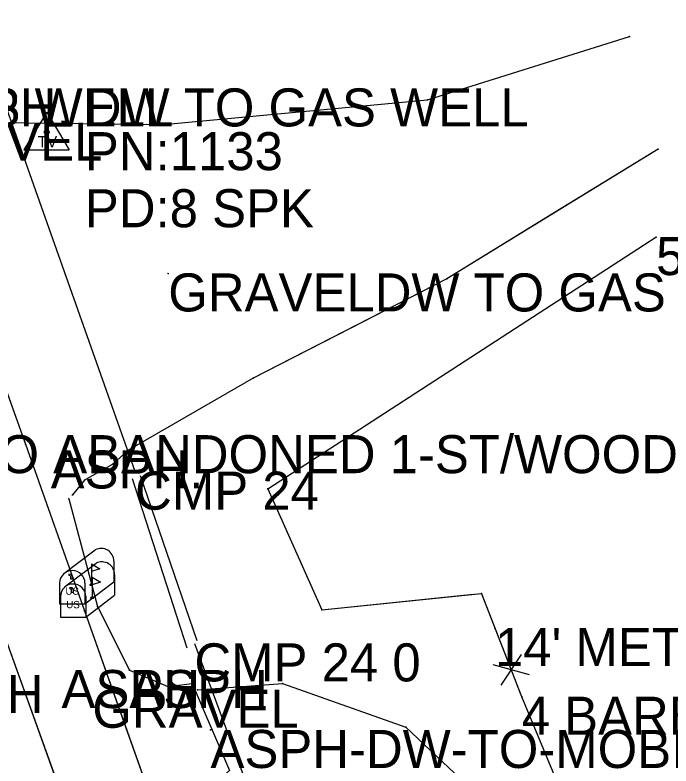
# Model space of a CAD drawing. Extents: x 1050807 to 1053552, y 395828 to 398415.
# Drawn here: x 1052635.6 to 1052721.8, y 396242.6 to 396341.3 of the extents above; entities that cross this region are included whole.
import ezdxf

# ---------------------------------------------------------------- set-up
doc = ezdxf.new("R2010")
doc.units = 0
for name, color, linetype in [('S_BREAKLINE_ANNOT', 7, 'Continuous'), ('S_DITCHLINE', 7, 'Continuous'), ('S_DRIVEWAY', 7, 'Continuous'), ('S_DRIVEWAY_ANNOT', 7, 'Continuous'), ('S_EDGE_PAVEMENT', 7, 'Continuous'), ('S_FENCE', 7, 'Continuous'), ('S_FENCE_ANNOT', 7, 'Continuous'), ('S_GATE_ANNOT', 7, 'Continuous'), ('S_MAILBOX', 7, 'Continuous'), ('S_MSC_PT_SYM', 7, 'Continuous'), ('S_PAVEMENT_CROWN', 7, 'Continuous'), ('S_RDW_PT_SYM', 7, 'Continuous'), ('S_SECONDARY_CTL', 7, 'Continuous'), ('S_SECONDARY_CTL_ANNOT', 7, 'Continuous'), ('S_SHOULDER', 7, 'Continuous'), ('S_SHOULDER_ANNOT', 7, 'Continuous'), ('S_SIDE_DRAIN', 7, 'Continuous'), ('S_SIDE_DRAIN_ANNOT', 7, 'Continuous'), ('S_SURVEY_TEXT_ANNOT', 7, 'Continuous')]:
    doc.layers.add(name, color=color, linetype=linetype)

msp = doc.modelspace()

# ---------------------------------------------------------------- linework, layer by layer
at = {"layer": 'S_DITCHLINE'}
for p, q in [((1052659.554, 396259.093), (1052652.113, 396280.771)), ((1052650.985, 396280.428), (1052658.169, 396258.14))]:
    msp.add_line(p, q, dxfattribs=at)
for points in [[(1052659.554, 396259.093), (1052652.113, 396280.771)], [(1052650.985, 396280.428), (1052658.169, 396258.14)]]:
    msp.add_lwpolyline(points, dxfattribs=at)
at = {"layer": 'S_DRIVEWAY'}
for p, q in [((1052689.815, 396330.179), (1052716.376, 396338.498)), ((1052655.11, 396326.952), (1052689.815, 396330.179)), ((1052633.806, 396327.202), (1052655.11, 396326.952)), ((1052720.133, 396323.689), (1052692.367, 396306.673)), ((1052692.367, 396306.673), (1052666.897, 396293.612)), ((1052666.897, 396293.612), (1052650.436, 396284.075)), ((1052650.432, 396284.099), (1052648.475, 396282.317)), ((1052648.475, 396282.317), (1052644.746, 396280.181)), ((1052644.746, 396280.181), (1052643.153, 396278.243)), ((1052650.633, 396255.24), (1052655.682, 396253.093)), ((1052655.682, 396253.093), (1052658.899, 396253.455)), ((1052658.899, 396253.455), (1052663.794, 396242.041)), ((1052659.599, 396252.648), (1052670.746, 396253.477)), ((1052670.746, 396253.477), (1052686.966, 396247.747)), ((1052686.966, 396247.747), (1052693.355, 396241.694))]:
    msp.add_line(p, q, dxfattribs=at)
for points in [[(1052633.806, 396327.202), (1052655.11, 396326.952), (1052672.463, 396328.566), (1052689.815, 396330.179), (1052703.095, 396334.339), (1052716.376, 396338.498)], [(1052720.133, 396323.689), (1052706.25, 396315.181), (1052692.367, 396306.673), (1052679.632, 396300.142), (1052666.897, 396293.612), (1052650.436, 396284.075)], [(1052650.432, 396284.099), (1052648.475, 396282.317), (1052644.746, 396280.181), (1052643.153, 396278.243)], [(1052650.633, 396255.24), (1052655.682, 396253.093), (1052658.899, 396253.455), (1052663.794, 396242.041), (1052658.163, 396237.039), (1052657.671, 396236.529)], [(1052659.599, 396252.648), (1052670.746, 396253.477), (1052686.966, 396247.747), (1052693.355, 396241.694), (1052703.814, 396231.564), (1052710.608, 396211.533), (1052717.403, 396191.501), (1052724.49, 396172.289), (1052731.576, 396153.078), (1052738.663, 396133.866), (1052745.75, 396114.654), (1052754.61, 396095.247), (1052763.47, 396075.839), (1052772.33, 396056.432), (1052781.19, 396037.024), (1052788.618, 396024.663), (1052796.046, 396012.301), (1052803.473, 395999.94), (1052810.901, 395987.578), (1052815.523, 395970.218), (1052820.461, 395954.627), (1052808.405, 395951.524)]]:
    msp.add_lwpolyline(points, dxfattribs=at)
at = {"layer": 'S_EDGE_PAVEMENT'}
for p, q in [((1052620.452, 396330.901), (1052636.983, 396284.917)), ((1052636.983, 396284.917), (1052644.723, 396263.019)), ((1052644.723, 396263.019), (1052655.116, 396233.764))]:
    msp.add_line(p, q, dxfattribs=at)
msp.add_lwpolyline([(1052574.206, 396459.412), (1052580.36, 396442.372), (1052586.514, 396425.332), (1052593.054, 396407.062), (1052599.594, 396388.791), (1052606.141, 396370.632), (1052612.688, 396352.473), (1052620.452, 396330.901), (1052628.718, 396307.909), (1052636.983, 396284.917), (1052644.723, 396263.019), (1052649.92, 396248.391), (1052655.116, 396233.764)], dxfattribs=at)
at = {"layer": 'S_FENCE'}
for p, q in [((1052668.814, 396279.063), (1052719.801, 396312.149)), ((1052668.814, 396279.038), (1052675.933, 396263.161)), ((1052675.933, 396263.161), (1052696.925, 396265.307)), ((1052699.491, 396253.229), (1052702.163, 396257.286)), ((1052703.198, 396254.615), (1052698.456, 396255.901))]:
    msp.add_line(p, q, dxfattribs=at)
for points in [[(1052668.814, 396279.038), (1052675.933, 396263.161)], [(1052675.933, 396263.161), (1052695.829, 396265.195)], [(1052721.509, 396192.743), (1052710.07, 396232.831), (1052702.193, 396251.73), (1052696.925, 396265.332)], [(1052700.309, 396256.594), (1052696.925, 396265.332)], [(1052714.931, 396215.794), (1052710.07, 396232.831), (1052702.193, 396251.73), (1052701.549, 396253.395)]]:
    msp.add_lwpolyline(points, dxfattribs=at)
at = {"layer": 'S_MAILBOX'}
for p, q in [((1052642.028, 396267.927), (1052646.162, 396271.035)), ((1052642.13, 396266.156), (1052646.265, 396269.264)), ((1052645.643, 396269.215), (1052645.643, 396266.5)), ((1052648.594, 396269.561), (1052648.594, 396266.846)), ((1052645.746, 396267.445), (1052645.746, 396264.73)), ((1052648.696, 396267.791), (1052648.696, 396265.076)), ((1052641.474, 396266.652), (1052641.474, 396263.937)), ((1052644.798, 396263.937), (1052648.594, 396266.846)), ((1052644.798, 396266.652), (1052644.798, 396263.937)), ((1052644.901, 396262.167), (1052648.696, 396265.076)), ((1052641.474, 396263.937), (1052644.798, 396263.937)), ((1052641.576, 396264.882), (1052641.576, 396262.167)), ((1052644.901, 396264.882), (1052644.901, 396262.167)), ((1052641.576, 396262.167), (1052644.901, 396262.167))]:
    msp.add_line(p, q, dxfattribs=at)
for points in [[(1052645.643, 396269.215), (1052646.751, 396268.55), (1052645.643, 396268.204)], [(1052642.658, 396267.768), (1052642.88, 396267.629), (1052642.88, 396267.241), (1052643.184, 396267.241), (1052643.184, 396267.601), (1052642.99, 396267.851), (1052642.658, 396267.795)], [(1052645.746, 396267.445), (1052646.854, 396266.78), (1052645.746, 396266.433)], [(1052642.761, 396265.997), (1052642.982, 396265.858), (1052642.982, 396265.471), (1052643.287, 396265.471), (1052643.287, 396265.831), (1052643.093, 396266.08), (1052642.761, 396266.025)]]:
    msp.add_lwpolyline(points, dxfattribs=at)
for centre, end in [((1052646.931, 396269.561), 117.57184), ((1052647.034, 396267.791), 117.57184), ((1052643.136, 396266.652), 180), ((1052643.238, 396264.882), 180)]:
    msp.add_arc(centre, 1.662, 0, end, dxfattribs=at)
for centre in [(1052645.643, 396266.5), (1052645.746, 396264.73)]:
    msp.add_ellipse(centre, major_axis=(0.145, 0.132), ratio=0.564646, dxfattribs=at)
at = {"layer": 'S_MSC_PT_SYM'}
for points in [[(1052719.851, 396312.149), (1052719.851, 396312.199), (1052719.851, 396312.149), (1052719.801, 396312.149), (1052719.851, 396312.149), (1052719.851, 396312.099), (1052719.851, 396312.149), (1052719.901, 396312.149)], [(1052655.747, 396307.37), (1052655.747, 396307.42), (1052655.747, 396307.37), (1052655.697, 396307.37), (1052655.747, 396307.37), (1052655.747, 396307.32), (1052655.747, 396307.37), (1052655.797, 396307.37)], [(1052668.814, 396279.038), (1052668.814, 396279.088), (1052668.814, 396279.038), (1052668.764, 396279.038), (1052668.814, 396279.038), (1052668.814, 396278.988), (1052668.814, 396279.038), (1052668.864, 396279.038)], [(1052696.925, 396265.307), (1052696.925, 396265.357), (1052696.925, 396265.307), (1052696.875, 396265.307), (1052696.925, 396265.307), (1052696.925, 396265.257), (1052696.925, 396265.307), (1052696.975, 396265.307)], [(1052675.933, 396263.161), (1052675.933, 396263.211), (1052675.933, 396263.161), (1052675.883, 396263.161), (1052675.933, 396263.161), (1052675.933, 396263.111), (1052675.933, 396263.161), (1052675.983, 396263.161)], [(1052698.682, 396260.752), (1052698.682, 396260.802), (1052698.682, 396260.752), (1052698.632, 396260.752), (1052698.682, 396260.752), (1052698.682, 396260.702), (1052698.682, 396260.752), (1052698.732, 396260.752)], [(1052702.193, 396251.73), (1052702.193, 396251.78), (1052702.193, 396251.73), (1052702.143, 396251.73), (1052702.193, 396251.73), (1052702.193, 396251.68), (1052702.193, 396251.73), (1052702.243, 396251.73)], [(1052661.294, 396247.359), (1052661.294, 396247.409), (1052661.294, 396247.359), (1052661.244, 396247.359), (1052661.294, 396247.359), (1052661.294, 396247.309), (1052661.294, 396247.359), (1052661.344, 396247.359)]]:
    msp.add_lwpolyline(points, dxfattribs=at)
at = {"layer": 'S_PAVEMENT_CROWN'}
msp.add_line((1052634.394, 396259.265), (1052644.906, 396230.007), dxfattribs=at)
msp.add_lwpolyline([(1052563.845, 396455.267), (1052570.025, 396438.384), (1052576.205, 396421.501), (1052582.809, 396403.173), (1052589.412, 396384.846), (1052595.833, 396366.903), (1052602.254, 396348.959), (1052609.906, 396326.87), (1052617.924, 396304.161), (1052625.942, 396281.452), (1052634.394, 396259.265), (1052639.65, 396244.636), (1052644.906, 396230.007)], dxfattribs=at)
at = {"layer": 'S_RDW_PT_SYM'}
for points in [[(1052716.376, 396338.498), (1052716.376, 396338.548), (1052716.376, 396338.498), (1052716.326, 396338.498), (1052716.376, 396338.498), (1052716.376, 396338.448), (1052716.376, 396338.498), (1052716.426, 396338.498)], [(1052689.815, 396330.179), (1052689.815, 396330.229), (1052689.815, 396330.179), (1052689.765, 396330.179), (1052689.815, 396330.179), (1052689.815, 396330.129), (1052689.815, 396330.179), (1052689.865, 396330.179)], [(1052655.11, 396326.952), (1052655.11, 396327.002), (1052655.11, 396326.952), (1052655.06, 396326.952), (1052655.11, 396326.952), (1052655.11, 396326.902), (1052655.11, 396326.952), (1052655.16, 396326.952)], [(1052720.133, 396323.689), (1052720.133, 396323.739), (1052720.133, 396323.689), (1052720.083, 396323.689), (1052720.133, 396323.689), (1052720.133, 396323.639), (1052720.133, 396323.689), (1052720.183, 396323.689)], [(1052692.367, 396306.673), (1052692.367, 396306.723), (1052692.367, 396306.673), (1052692.317, 396306.673), (1052692.367, 396306.673), (1052692.367, 396306.623), (1052692.367, 396306.673), (1052692.417, 396306.673)], [(1052666.897, 396293.612), (1052666.897, 396293.662), (1052666.897, 396293.612), (1052666.847, 396293.612), (1052666.897, 396293.612), (1052666.897, 396293.562), (1052666.897, 396293.612), (1052666.947, 396293.612)], [(1052636.983, 396284.917), (1052636.983, 396284.967), (1052636.983, 396284.917), (1052636.933, 396284.917), (1052636.983, 396284.917), (1052636.983, 396284.867), (1052636.983, 396284.917), (1052637.033, 396284.917)], [(1052650.432, 396284.099), (1052650.432, 396284.149), (1052650.432, 396284.099), (1052650.382, 396284.099), (1052650.432, 396284.099), (1052650.432, 396284.049), (1052650.432, 396284.099), (1052650.482, 396284.099)], [(1052650.436, 396284.075), (1052650.436, 396284.125), (1052650.436, 396284.075), (1052650.386, 396284.075), (1052650.436, 396284.075), (1052650.436, 396284.025), (1052650.436, 396284.075), (1052650.486, 396284.075)], [(1052648.475, 396282.317), (1052648.475, 396282.367), (1052648.475, 396282.317), (1052648.425, 396282.317), (1052648.475, 396282.317), (1052648.475, 396282.267), (1052648.475, 396282.317), (1052648.525, 396282.317)], [(1052644.746, 396280.181), (1052644.746, 396280.231), (1052644.746, 396280.181), (1052644.696, 396280.181), (1052644.746, 396280.181), (1052644.746, 396280.131), (1052644.746, 396280.181), (1052644.796, 396280.181)], [(1052642.667, 396277.739), (1052642.667, 396277.789), (1052642.667, 396277.739), (1052642.617, 396277.739), (1052642.667, 396277.739), (1052642.667, 396277.689), (1052642.667, 396277.739), (1052642.717, 396277.739)], [(1052643.153, 396278.243), (1052643.153, 396278.293), (1052643.153, 396278.243), (1052643.103, 396278.243), (1052643.153, 396278.243), (1052643.153, 396278.193), (1052643.153, 396278.243), (1052643.203, 396278.243)], [(1052644.723, 396263.019), (1052644.723, 396263.069), (1052644.723, 396263.019), (1052644.673, 396263.019), (1052644.723, 396263.019), (1052644.723, 396262.969), (1052644.723, 396263.019), (1052644.773, 396263.019)], [(1052646.452, 396263.595), (1052646.452, 396263.645), (1052646.452, 396263.595), (1052646.402, 396263.595), (1052646.452, 396263.595), (1052646.452, 396263.545), (1052646.452, 396263.595), (1052646.502, 396263.595)], [(1052650.633, 396255.24), (1052650.633, 396255.29), (1052650.633, 396255.24), (1052650.583, 396255.24), (1052650.633, 396255.24), (1052650.633, 396255.19), (1052650.633, 396255.24), (1052650.683, 396255.24)], [(1052650.633, 396255.24), (1052650.633, 396255.29), (1052650.633, 396255.24), (1052650.583, 396255.24), (1052650.633, 396255.24), (1052650.633, 396255.19), (1052650.633, 396255.24), (1052650.683, 396255.24)], [(1052655.682, 396253.093), (1052655.682, 396253.143), (1052655.682, 396253.093), (1052655.632, 396253.093), (1052655.682, 396253.093), (1052655.682, 396253.043), (1052655.682, 396253.093), (1052655.732, 396253.093)], [(1052658.899, 396253.455), (1052658.899, 396253.505), (1052658.899, 396253.455), (1052658.849, 396253.455), (1052658.899, 396253.455), (1052658.899, 396253.405), (1052658.899, 396253.455), (1052658.949, 396253.455)], [(1052670.746, 396253.477), (1052670.746, 396253.527), (1052670.746, 396253.477), (1052670.696, 396253.477), (1052670.746, 396253.477), (1052670.746, 396253.427), (1052670.746, 396253.477), (1052670.796, 396253.477)], [(1052659.599, 396252.648), (1052659.599, 396252.698), (1052659.599, 396252.648), (1052659.549, 396252.648), (1052659.599, 396252.648), (1052659.599, 396252.598), (1052659.599, 396252.648), (1052659.649, 396252.648)], [(1052686.966, 396247.747), (1052686.966, 396247.797), (1052686.966, 396247.747), (1052686.916, 396247.747), (1052686.966, 396247.747), (1052686.966, 396247.697), (1052686.966, 396247.747), (1052687.016, 396247.747)]]:
    msp.add_lwpolyline(points, dxfattribs=at)
at = {"layer": 'S_SECONDARY_CTL'}
for p, q in [((1052639.786, 396328.546), (1052636.776, 396323.593)), ((1052639.786, 396328.546), (1052642.734, 396323.593)), ((1052636.776, 396323.593), (1052642.734, 396323.593))]:
    msp.add_line(p, q, dxfattribs=at)
for radius in [0.311, 0.183, 0.103]:
    msp.add_circle((1052639.786, 396325.936), radius, dxfattribs=at)
at = {"layer": 'S_SHOULDER'}
for p, q in [((1052642.667, 396277.739), (1052646.452, 396263.595)), ((1052646.452, 396263.595), (1052650.633, 396255.24))]:
    msp.add_line(p, q, dxfattribs=at)
msp.add_lwpolyline([(1052642.667, 396277.739), (1052646.452, 396263.595), (1052650.633, 396255.24)], dxfattribs=at)
at = {"layer": 'S_SIDE_DRAIN'}
for p, q in [((1052651.396, 396281.312), (1052632.813, 396333.803)), ((1052659.185, 396258.741), (1052667.74, 396235.638))]:
    msp.add_line(p, q, dxfattribs=at)

# ---------------------------------------------------------------- texts
at = {"layer": 'S_BREAKLINE_ANNOT'}
for s, p in [('5 BARB WOOD & METAL POST GOOD', (1052719.851, 396307.149)), ('4 BARB STEEL POST GOOD', (1052702.193, 396246.73))]:
    msp.add_text(s, height=5, dxfattribs=at).set_placement(p)
at = {"layer": 'S_DRIVEWAY_ANNOT'}
for s, p in [('ASPH. DW TO GAS WELL', (1052576.148, 396326.689)), ('GRAVEL', (1052619.969, 396322.202)), ('ASPH.', (1052640.295, 396279.099)), ('ASPH', (1052641.716, 396250.24)), ('GRAVEL', (1052645.762, 396247.648))]:
    msp.add_text(s, height=5, dxfattribs=at).set_placement(p)
at = {"layer": 'S_FENCE_ANNOT'}
for s, p in [('5 BARB WOOD & METAL POST GOOD', (1052719.851, 396307.149)), ('4 BARB STEEL POST GOOD', (1052702.193, 396246.73))]:
    msp.add_text(s, height=5, dxfattribs=at).set_placement(p)
at = {"layer": 'S_GATE_ANNOT'}
msp.add_text("14' METAL", height=5, dxfattribs=at).set_placement((1052698.682, 396255.752))
at = {"layer": 'S_MAILBOX'}
for p in [(1052642.237, 396265.131), (1052642.34, 396263.361)]:
    msp.add_text('US', height=0.96, dxfattribs=at).set_placement(p)
at = {"layer": 'S_SECONDARY_CTL'}
msp.add_text('TV', height=1.5, dxfattribs=at).set_placement((1052638.582, 396323.925))
at = {"layer": 'S_SECONDARY_CTL_ANNOT'}
for s, p in [('PN:1133', (1052644.786, 396320.936)), ('PD:8 SPK', (1052644.786, 396313.436))]:
    msp.add_text(s, height=5, dxfattribs=at).set_placement(p)
at = {"layer": 'S_SHOULDER_ANNOT'}
for s, p in [('ASPH. DW TO GAS WELL', (1052622.857, 396326.689)), ('ASPH', (1052650.633, 396250.24)), ('ASPH', (1052621.144, 396249.577))]:
    msp.add_text(s, height=5, dxfattribs=at).set_placement(p)
at = {"layer": 'S_SIDE_DRAIN_ANNOT'}
for s, p in [('CMP 24', (1052651.396, 396276.312)), ('CMP 24 0', (1052659.185, 396253.741))]:
    msp.add_text(s, height=5, dxfattribs=at).set_placement(p)
at = {"layer": 'S_SURVEY_TEXT_ANNOT'}
for s, p in [('GRAVELDW TO GAS WELL', (1052655.747, 396302.37)), ('ASPH DW TO ABANDONED 1-ST/WOOD ', (1052596.423, 396281.11)), ('ASPH-DW-TO-MOBILE-HOME', (1052661.294, 396242.359))]:
    msp.add_text(s, height=5, dxfattribs=at).set_placement(p)

doc.saveas('drawing.dxf')
